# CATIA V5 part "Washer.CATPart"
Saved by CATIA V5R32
Part number: washer
Bounding box of the stored display mesh (mm): x -24 to 24, y -23.825 to 23.825, z 0 to 3
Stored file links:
  D:\PROJECTS\Project 2022\CATIA V5 6R 2022\Resources\Part Files\c14_catia_v5_6r2022_prt\c14-catia-v5-6r2022-figr-14-26 & 27\Part & Asm\Washer.CATPart
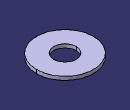
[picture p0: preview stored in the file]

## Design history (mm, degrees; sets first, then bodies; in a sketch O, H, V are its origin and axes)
Body1 (main body)
  Sketch1 on xy-plane, origin (0, 0, 0), H (1, 0, 0), V (0, 1, 0)
    circle A1 centre (0, 0) radius 24
    circle A2 centre (0, 0) radius 9.5
    radius A1 = 24
    radius A2 = 9.5
  Pad1: profile Sketch1, direction (0, 0, 1), length 3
